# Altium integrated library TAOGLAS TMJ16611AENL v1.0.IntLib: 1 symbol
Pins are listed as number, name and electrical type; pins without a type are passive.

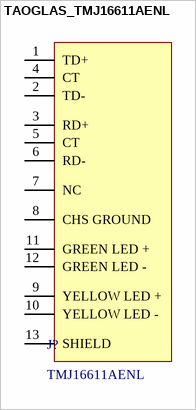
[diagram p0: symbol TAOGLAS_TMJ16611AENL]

## TAOGLAS_TMJ16611AENL
designator J?, comment TMJ16611AENL
RJ45 connector with integrated magnetics 10/100Base-T Single Port Tab-UP with right angle THT mount and LEDs; ComponentLibStatus: Created; MFG: Taoglas; Temp_High: +85C; Temp_Low: -40C
footprint TAOGLAS_TMJ16611AENL (RJ45 connector with integrated magnetics 10/100Base-T Single Port Tab-UP with right angle THT mount and LEDs)
pins: 1 TD+, 2 TD-, 3 RD+, 4 CT, 5 CT, 6 RD-, 7 NC, 8 CHS GROUND, 9 YELLOW LED +, 10 YELLOW LED -, 11 GREEN LED +, 12 GREEN LED -, 13 SHIELD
